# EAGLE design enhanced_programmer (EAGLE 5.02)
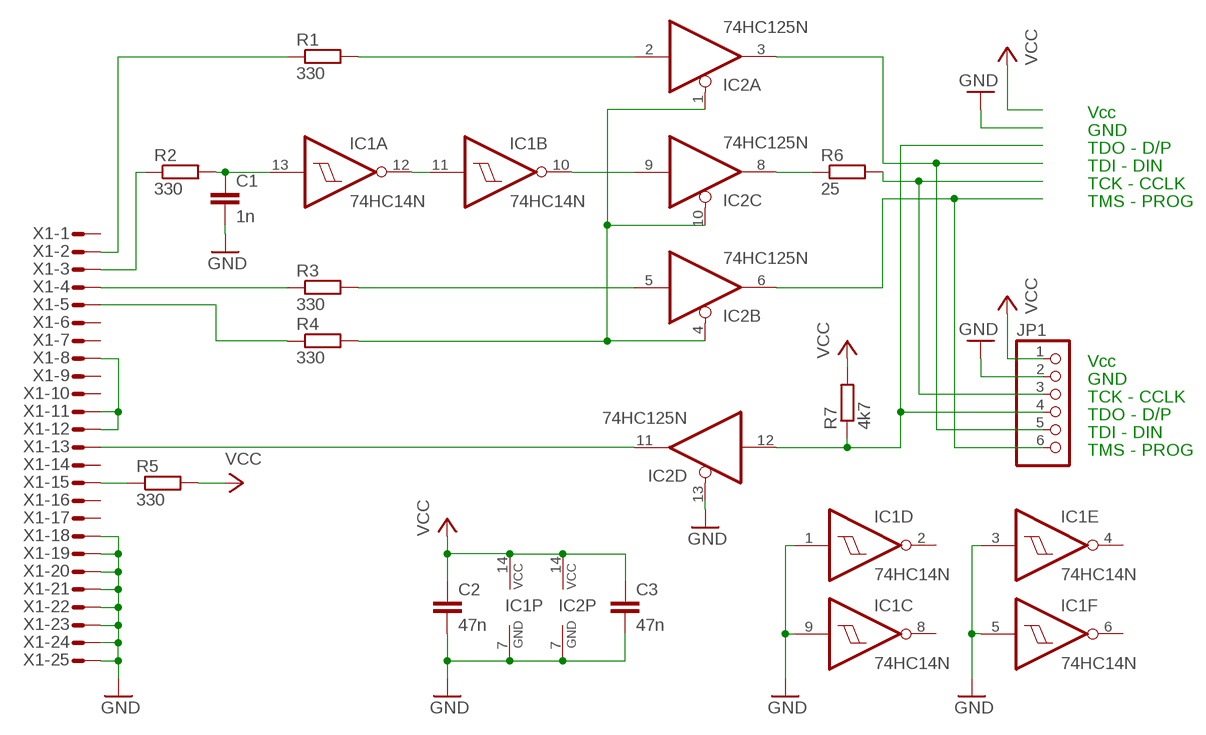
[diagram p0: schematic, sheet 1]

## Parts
C1  1n  C-EU025-025X050  [C025-025X050]
C2  47n  C-EU025-025X050  [C025-025X050]
C3  47n  C-EU025-025X050  [C025-025X050]
IC1  74HC14N  [DIL14]
IC2  74HC125N  [DIL14]
JP1  PINHD-1X6  [1X06]
R1  330  R-EU_0207/10  [0207/10]
R2  330  R-EU_0207/10  [0207/10]
R3  330  R-EU_0207/10  [0207/10]
R4  330  R-EU_0207/10  [0207/10]
R5  330  R-EU_0207/10  [0207/10]
R6  25  R-EU_0207/10  [0207/10]
R7  4k7  R-EU_0207/10  [0207/10]
X1  M25-182S  [182-025-MALE]

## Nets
GND: C1.2 C2.2 C3.2 IC1.1(D:I) IC1.3(E:I) IC1.5(F:I) IC1.7(P:GND) IC1.9(C:I) IC2.7(P:GND) IC2.13(D:OE) JP1.2 X1.18 X1.19 X1.20 X1.21 X1.22 X1.23 X1.24 X1.25
N$2: X1.8 X1.11 X1.12
N$3: R5.1 X1.15
N$4: IC2.1(A:OE) IC2.4(B:OE) IC2.10(C:OE) R4.2
N$5: R4.1 X1.5
N$6: IC2.2(A:I) R1.2
N$7: C1.1 IC1.13(A:I) R2.2
N$8: IC2.5(B:I) R3.2
N$9: R1.1 X1.2
N$10: R2.1 X1.3
N$11: IC1.11(B:I) IC1.12(A:O)
N$12: IC1.10(B:O) IC2.9(C:I)
N$13: R3.1 X1.4
N$14: IC2.8(C:O) R6.1
N$15: IC2.11(D:O) X1.13
TCK/CCLK: JP1.3 R6.2
TDI/DIN: IC2.3(A:O) JP1.5
TDO/DONE: IC2.12(D:I) JP1.4 R7.1
TMS/PROG: IC2.6(B:O) JP1.6
VCC: C2.1 C3.1 IC1.14(P:VCC) IC2.14(P:VCC) JP1.1 R5.2 R7.2
Unconnected: IC1.2(D:O) IC1.4(E:O) IC1.6(F:O) IC1.8(C:O) X1.1 X1.6 X1.7 X1.9 X1.10 X1.14 X1.16 X1.17

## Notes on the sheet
- Vcc
- GND
- TDO - D/P
- TDI - DIN
- TCK - CCLK
- TMS - PROG
- Vcc
- GND
- TCK - CCLK
- TDO - D/P
- TDI - DIN
- TMS - PROG

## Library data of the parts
C1-C3 = rcl:C-EU: CAPACITOR, European symbol
IC1 = 74xx-eu:74*14: Hex schmitt trigger INVERTER
IC2 = 74xx-eu:74*125: Quad bus BUFFER, 3-state
JP1 = pinhead:PINHD-1X6: PIN HEADER
R1-R7 = rcl:R-EU_: RESISTOR, European symbol
X1 = con-subd:M25?S: SUB-D

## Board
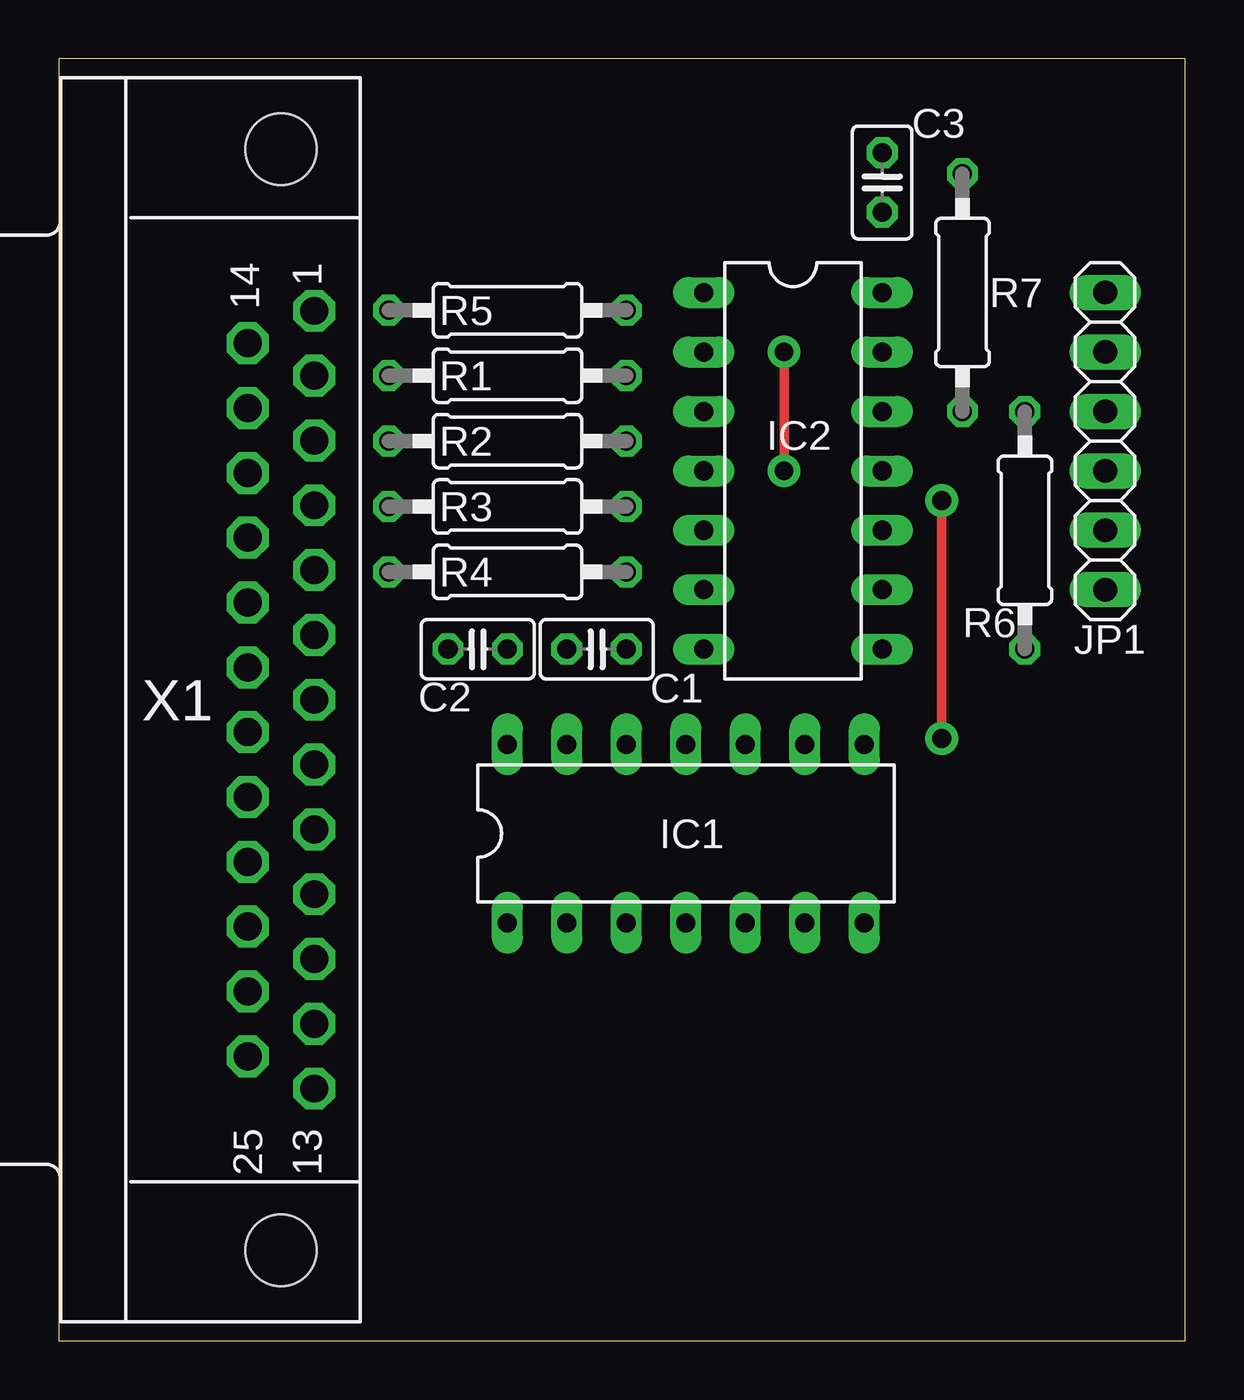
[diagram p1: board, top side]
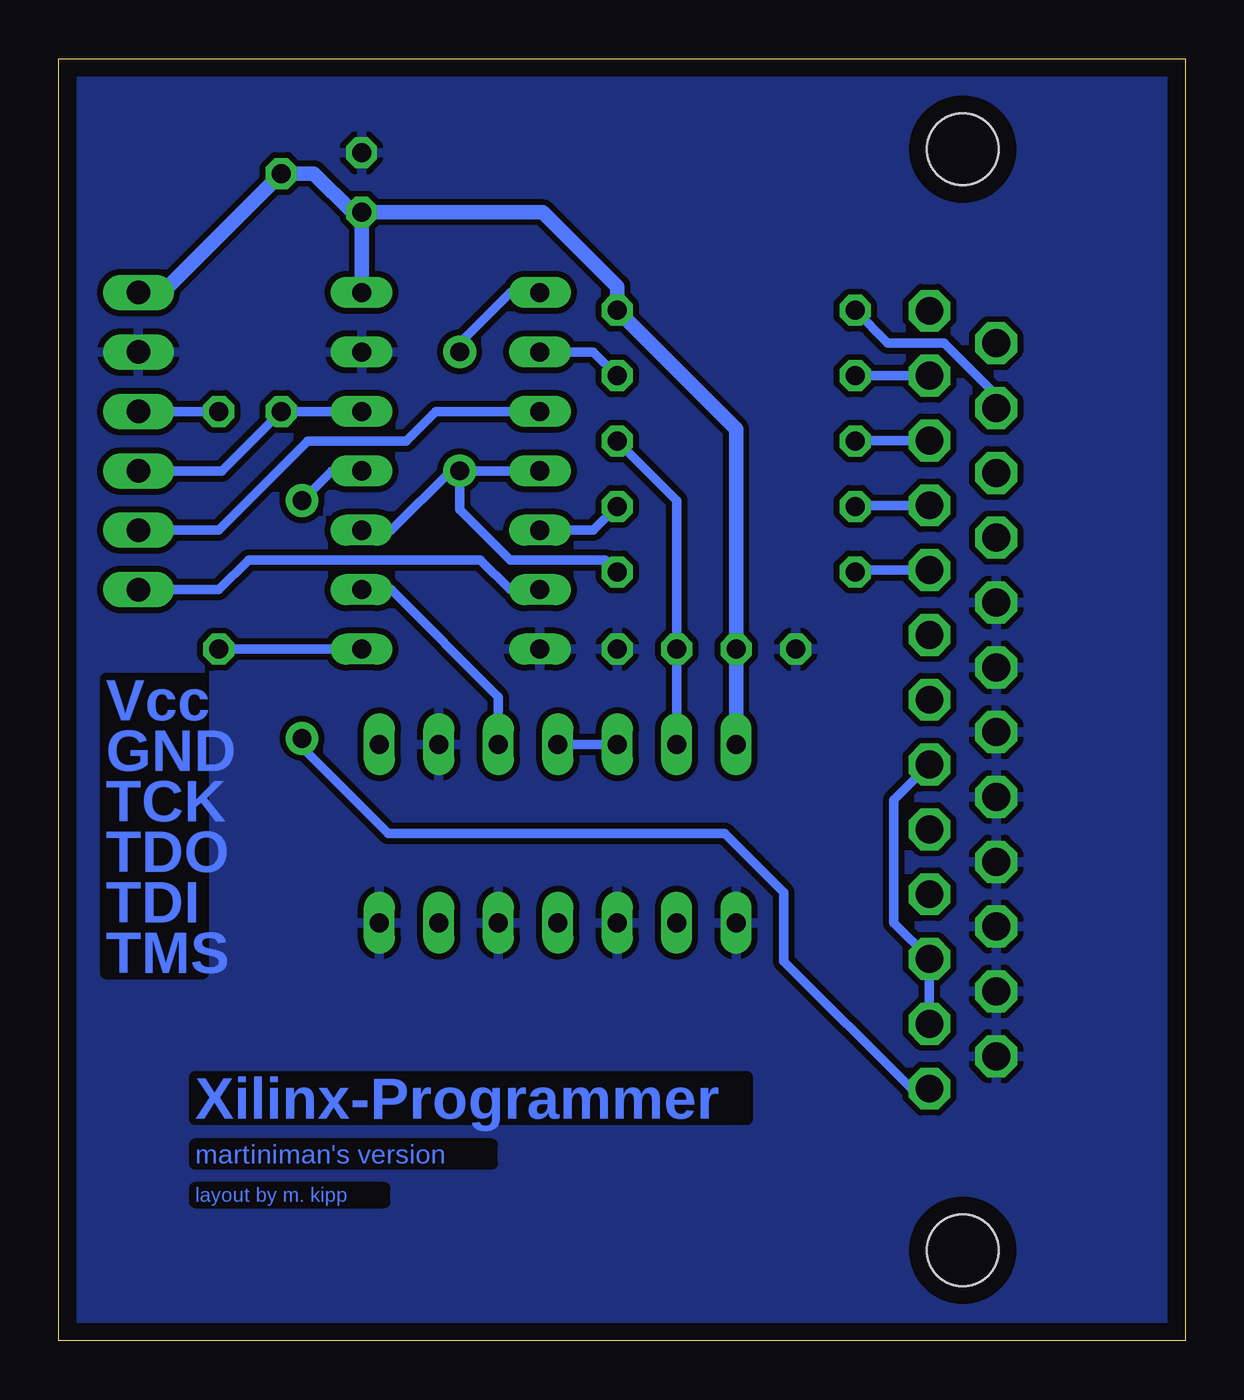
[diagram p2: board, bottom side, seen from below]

Size 48.11 x 54.79 mm. Coordinates in mm from the lower left corner, seen from the top.
Outline: 0,0 48.11,0 48.11,54.79 0,54.79 0,0
Copper layers (1*16): Top 0.035mm / dielectric 1.5mm / Bottom 0.035mm
Design rules "default *": minimum track width 10mil, minimum drill 24mil, track to track 10mil, track to pad 10mil, pad to pad 10mil, via to via 10mil, smd to smd 10mil, copper to edge 30mil, drill to drill 8mil, minimum pad ring 10mil, minimum via ring 8mil, stop-mask expansion 4mil, vias tented up to drill 0mil, thermal gap 10mil

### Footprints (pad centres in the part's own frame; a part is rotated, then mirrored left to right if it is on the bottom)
C025-025X050 = drill 0.813 octagon: 1 -1.27,0; 2 1.27,0
DIL14 = drill 0.813 long: 1 -7.62,-3.81; 2 -5.08,-3.81; 3 -2.54,-3.81; 4 0,-3.81; 5 2.54,-3.81; 6 5.08,-3.81; 7 7.62,-3.81; 8 7.62,3.81; 9 5.08,3.81; 10 2.54,3.81; 11 0,3.81; 12 -2.54,3.81; 13 -5.08,3.81; 14 -7.62,3.81
1X06 = drill 1.016 long: 1 -6.35,0; 2 -3.81,0; 3 -1.27,0; 4 1.27,0; 5 3.81,0; 6 6.35,0
0207/10 = drill 0.813 octagon: 1 -5.08,0; 2 5.08,0
182-025-MALE = drill 1.194 pad 1.524 octagon: 1 -16.612,10.923; 2 -13.843,10.923; 3 -11.074,10.923; 4 -8.306,10.923; 5 -5.537,10.923; 6 -2.769,10.923; 7 0,10.923; 8 2.769,10.923; 9 5.537,10.923; 10 8.306,10.923; 11 11.074,10.923; 12 13.843,10.923; 13 16.612,10.923; 14 -15.227,8.08; 15 -12.459,8.08; 16 -9.69,8.08; 17 -6.921,8.08; 18 -4.153,8.08; 19 -1.384,8.08; 20 1.384,8.08; 21 4.153,8.08; 22 6.921,8.08; 23 9.69,8.08; 24 12.459,8.08; 25 15.227,8.08 | hole 3.048: -23.52,9.501; 23.52,9.501

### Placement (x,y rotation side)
C1  22.98,29.55 0 top
C2  17.9,29.55 180 top
C3  35.17,49.49 90 top
IC1  26.79,21.68 0 top
IC2  31.36,37.17 270 top
JP1  44.7,38.44 270 top
R1  19.17,41.24 0 top
R2  19.17,38.44 0 top
R3  19.17,35.65 0 top
R4  19.17,32.86 0 top
R5  19.17,44.03 0 top
R6  41.27,34.63 90 top
R7  38.6,44.79 90 top
X1  -0.01,27.39 270 top

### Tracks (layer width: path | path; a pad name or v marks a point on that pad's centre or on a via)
GND
  pour Bottom: 0.25,54.57 47.87,54.57 47.87,0.22 0.25,0.22
N$2
  Bottom 0.406: X1.8 12.44,23.1 12.44,17.87 10.92,16.34 X1.11 X1.12
N$3
  Bottom 0.406: X1.15 8.12,39.9 8.12,40.48 10.28,42.63 12.69,42.63 R5.1
N$4  (via drill 0.8 pad 1.4)
  Top 0.406: v30.98,37.17 v30.98,42.25
  Bottom 0.406: v30.98,37.17 IC2.4 | v30.98,37.17 31.36,37.17 33.9,34.63 IC2.10 | v30.98,42.25 30.98,42.63 28.82,44.79 IC2.1 | R4.2 24.76,33.36 28.82,33.36 30.98,35.52 v30.98,37.17
N$5
  Bottom 0.406: X1.5 14.09,32.93 R4.1
N$6
  Bottom 0.406: R1.2 25.27,42.25 IC2.2
N$7
  Bottom 0.406: IC1.13 C1.1 21.71,35.9 R2.2
N$8
  Bottom 0.406: R3.2 25.27,34.63 IC2.5
N$9
  Bottom 0.406: X1.2 R1.1
N$10
  Bottom 0.406: X1.3 14.09,38.47 R2.1
N$11
  Bottom 0.406: IC1.12 IC1.11
N$12
  Bottom 0.406: IC1.10 29.33,27.52 33.9,32.09 IC2.9
N$13
  Bottom 0.406: X1.4 14.09,35.7 R3.1
N$14
  Bottom 0.406: IC2.8 R6.1
N$15  (via drill 0.8 pad 1.4)
  Top 0.406: v37.71,25.74 v37.71,35.9
  Bottom 0.406: X1.13 11.7,10.78 17.14,16.22 17.14,19.16 19.66,21.68 34.03,21.68 37.71,25.36 v37.71,25.74 | v37.71,35.9 36.44,37.17 IC2.11
TCK/CCLK
  Bottom 0.406: R6.2 JP1.3
TDI/DIN
  Bottom 0.406: IC2.3 32,39.71 33.27,38.44 37.46,38.44 41.27,34.63 JP1.5
TDO/DONE
  Bottom 0.406: IC2.12 R7.1 41.14,37.17 JP1.4
TMS/PROG
  Bottom 0.406: IC2.6 28.82,32.09 30.09,33.36 40,33.36 41.27,32.09 JP1.6
VCC
  Bottom 0.61: C3.1 35.55,48.22 37.21,49.87 R7.2 43.68,44.79 JP1.1 | C3.1 IC2.14 | C3.1 27.43,48.22 24.25,45.05 R5.2 19.17,38.95 C2.1 IC1.14

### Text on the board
Bottom: Vcc | GND | TCK | TDO | TDI | TMS | Xilinx-Programmer | martiniman's version | layout by m. kipp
